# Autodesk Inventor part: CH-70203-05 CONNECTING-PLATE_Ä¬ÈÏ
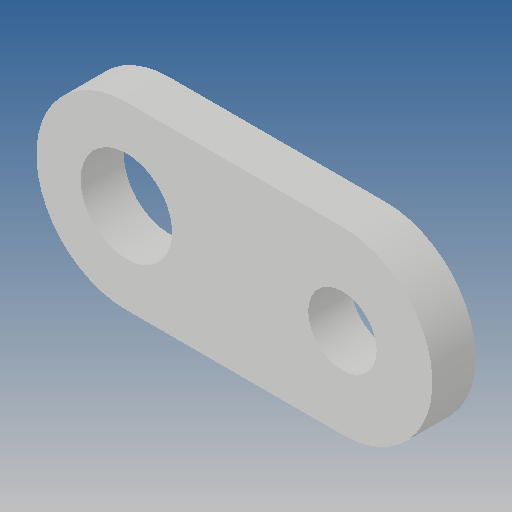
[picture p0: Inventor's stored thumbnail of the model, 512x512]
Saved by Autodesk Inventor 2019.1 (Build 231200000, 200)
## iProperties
Created: 2010-06
Part Number: CH-70203-05 CONNECTING-PLATE_Ä¬ÈÏ
Material: Ogólny
Document SubType Name: Modeling
Designer: CADENGINEERING4
Density: 1 g/cm^3
Appearance: Domyślna
Author: CADENGINEERING4
Revision Number: ÈÎºÎ
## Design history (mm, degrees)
feature "NONE"
node "Bryła1"
